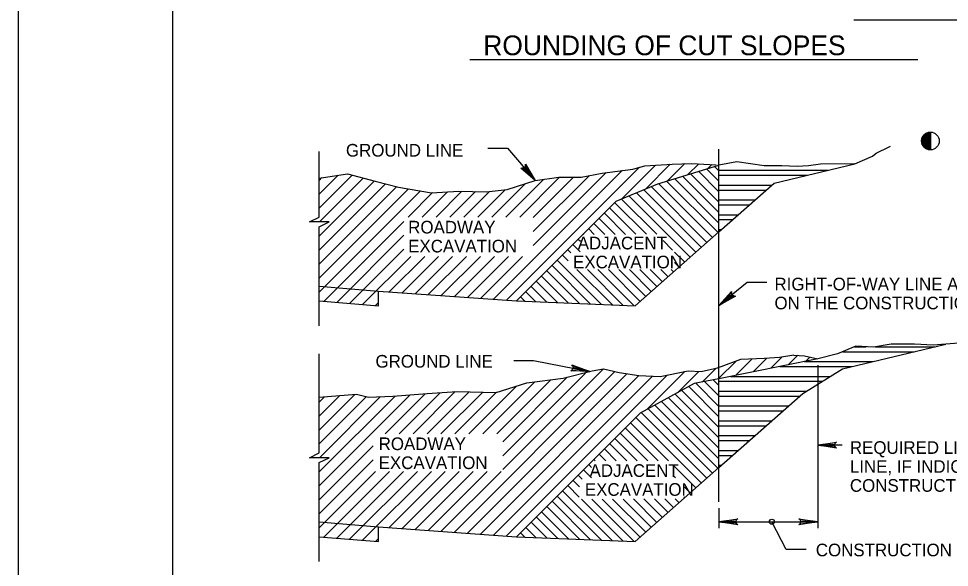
# Model space of a CAD drawing. Extents: x 240 to 1147, y 662 to 1256.
# Drawn here: x 240.4 to 476.2, y 959.9 to 1098.9 of the extents above; entities that cross this region are included whole.
import ezdxf

# ---------------------------------------------------------------- set-up
doc = ezdxf.new("R2010")
doc.units = 0
for name, color, linetype in [('1', 7, 'Continuous'), ('2', 7, 'Continuous'), ('3', 7, 'Continuous'), ('PLT-BNDY', 7, 'Continuous')]:
    doc.layers.add(name, color=color, linetype=linetype)

msp = doc.modelspace()

# ---------------------------------------------------------------- linework, layer by layer
at = {"layer": '1'}
for points in [[(1065.4425, 677.018625), (1065.4425, 1241.018625), (279.4425, 1241.018625), (279.4425, 677.018625), (1065.4425, 677.018625), (1065.4425, 703.377625), (865.4425, 703.377625), (865.4425, 768.055125), (1065.4425, 768.055125), (1065.4425, 797.018625), (865.4425, 797.018625), (865.4425, 677.018625), (944.244, 677.018625), (944.244, 703.377625), (944.244, 677.018625), (1021.244, 677.018625), (1021.244, 703.377625), (1021.244, 691.061125), (1065.4425, 691.061125)], [(368.784, 1061.695875), (368.6445, 1061.352125), (371.309, 1057.877125), (368.784, 1061.695875), (368.784, 1062.002125), (371.309, 1057.877125), (368.30075, 1061.052125), (367.94875, 1060.960375), (371.309, 1057.877125), (367.62375, 1061.006125), (367.94875, 1060.960375)], [(421.69875, 1028.637375), (421.359, 1028.783375), (417.82575, 1026.197875), (421.69875, 1028.637375), (422.005, 1028.631125), (417.82575, 1026.197875), (421.0675, 1029.135375), (420.984, 1029.487375), (417.82575, 1026.197875), (421.03625, 1029.812375), (420.984, 1029.487375)], [(380.75075, 1010.985375), (380.85275, 1010.629125), (385.09875, 1009.558375), (380.75075, 1010.985375), (380.559, 1011.224875), (385.09875, 1009.558375), (380.7695, 1010.181125), (380.55075, 1009.891625), (385.09875, 1009.558375), (380.2675, 1009.724875), (380.55075, 1009.891625)], [(447.3675, 990.327125), (447.1965, 990.656125), (442.82575, 990.897875), (447.3675, 990.327125), (447.59875, 990.127125), (442.82575, 990.897875), (447.1945, 991.112375), (447.35275, 991.437375), (442.82575, 990.897875), (447.59875, 991.656125), (447.35275, 991.437375)], [(422.3675, 970.916625), (422.1965, 971.245875), (417.82575, 971.487375), (422.3675, 970.916625), (422.59875, 970.718625), (417.82575, 971.487375), (422.1945, 971.702125), (422.35275, 972.029125), (417.82575, 971.487375), (422.59875, 972.245875), (422.35275, 972.029125)], [(438.28625, 972.056125), (438.455, 971.729125), (442.82575, 971.487375), (438.28625, 972.056125), (438.05275, 972.256125), (442.82575, 971.487375), (438.459, 971.270875), (438.29875, 970.945875), (442.82575, 971.487375), (438.05275, 970.729125), (438.29875, 970.945875)]]:
    msp.add_lwpolyline(points, dxfattribs=at)
at = {"layer": '2'}
for p, q in [((451.96525, 1098.531125), (499.31125, 1098.531125)), ((354.734, 1088.547875), (468.1715, 1088.547875)), ((471.3675, 1070.122875), (471.3675, 1065.633375)), ((417.82575, 976.524875), (417.82575, 1065.810375)), ((364.00275, 1027.560375), (397.657, 1061.216625)), ((393.16325, 1053.185375), (401.73, 1061.752125)), ((399.282, 1055.768625), (405.48825, 1061.974875)), ((402.3195, 1057.052125), (417.82575, 1061.799875)), ((404.88625, 1057.837375), (409.18825, 1062.139625)), ((409.982, 1059.397875), (412.68825, 1062.104125)), ((415.07775, 1060.958375), (416.02575, 1061.906125)), ((417.82575, 1060.352125), (416.7175, 1061.460375)), ((431.8195, 1057.222875), (452.2715, 1062.091625)), ((316.57575, 1050.843625), (324.9465, 1059.214625)), ((316.57575, 1054.381125), (321.382, 1059.185375)), ((316.57575, 1057.916625), (317.255, 1058.593625)), ((360.70275, 1027.795875), (393.3175, 1060.410375)), ((367.37775, 1048.612375), (377.4675, 1058.704125)), ((370.80275, 1041.431125), (389.23825, 1059.868625)), ((370.80275, 1044.966625), (384.92575, 1059.089625)), ((370.80275, 1048.502125), (381.00275, 1058.704125)), ((417.82575, 1049.743625), (408.5965, 1058.972875)), ((417.82575, 1052.395875), (410.62775, 1059.595875)), ((417.82575, 1055.047875), (412.657, 1060.216625)), ((417.82575, 1057.699875), (414.68825, 1060.837375)), ((417.82575, 1060.462375), (445.43, 1060.462375)), ((417.82575, 1059.212375), (440.18, 1059.212375)), ((316.57575, 1043.772875), (330.52375, 1057.720875)), ((316.57575, 1040.237375), (333.36125, 1057.024875)), ((316.57575, 1036.702125), (336.20275, 1056.329125)), ((316.6425, 1047.374875), (327.734, 1058.468625)), ((360.307, 1048.612375), (368.76125, 1057.068625)), ((363.8425, 1048.612375), (373.39875, 1058.168625)), ((391.8175, 1052.616625), (402.3195, 1057.052125)), ((414.77775, 1042.187375), (400.62775, 1056.337375)), ((416.18625, 1043.429125), (402.507, 1057.110375)), ((417.5945, 1044.672875), (404.53625, 1057.731125)), ((417.82575, 1047.093625), (406.5675, 1058.352125)), ((417.82575, 1044.874875), (431.8195, 1057.222875)), ((417.82575, 1056.712375), (431.2425, 1056.712375)), ((316.57575, 1033.166625), (339.1925, 1055.783375)), ((316.57575, 1029.631125), (342.207, 1055.262375)), ((339.0925, 1048.612375), (345.28, 1054.799875)), ((342.62775, 1048.612375), (349.03825, 1055.022875)), ((346.16325, 1048.612375), (352.7215, 1055.170875)), ((349.69875, 1048.612375), (356.155, 1055.068625)), ((353.234, 1048.612375), (359.709, 1055.087375)), ((356.7715, 1048.612375), (363.71325, 1055.554125)), ((410.55275, 1038.458375), (395.034, 1053.974875)), ((411.96125, 1039.699875), (396.89875, 1054.762375)), ((413.3695, 1040.943625), (398.76125, 1055.549875)), ((417.82575, 1055.462375), (429.82575, 1055.462375)), ((391.8175, 1052.616625), (366.57575, 1027.374875)), ((399.43625, 1044.268625), (391.45275, 1052.252125)), ((402.07375, 1044.283375), (393.1695, 1053.187375)), ((417.82575, 1052.962375), (426.9925, 1052.962375)), ((417.82575, 1051.712375), (425.57575, 1051.712375)), ((394.16125, 1044.241625), (388.80075, 1049.599875)), ((396.79875, 1044.256125), (390.12775, 1050.927125)), ((417.82575, 1049.212375), (422.7425, 1049.212375)), ((317.757, 1027.277125), (338.01125, 1047.531125)), ((388.884, 1044.214625), (386.15075, 1046.949875)), ((391.52375, 1044.229125), (387.47575, 1048.274875)), ((417.82575, 1047.962375), (421.32575, 1047.962375)), ((386.2465, 1044.199875), (384.82375, 1045.624875)), ((396.57575, 1026.124875), (417.82575, 1044.874875)), ((417.82575, 1045.462375), (418.4925, 1045.462375)), ((321.0215, 1027.006125), (338.01125, 1043.995875)), ((382.72375, 1042.420875), (382.1715, 1042.972875)), ((383.609, 1044.187375), (383.49875, 1044.297875)), ((406.082, 1040.274875), (403.69875, 1042.658375)), ((324.284, 1026.733375), (338.01125, 1040.460375)), ((380.30275, 1039.537375), (379.5195, 1040.320875)), ((382.66525, 1039.829125), (380.8465, 1041.645875)), ((409.1425, 1037.214625), (406.582, 1039.774875)), ((327.54875, 1026.462375), (339.759, 1038.672875)), ((334.30275, 1029.681125), (343.2945, 1038.672875)), ((337.60275, 1029.445875), (346.83, 1038.672875)), ((340.90275, 1029.210375), (350.36525, 1038.672875)), ((344.20275, 1028.974875), (353.90075, 1038.672875)), ((347.50275, 1028.737375), (357.43625, 1038.672875)), ((350.80275, 1028.502125), (360.9715, 1038.672875)), ((354.10275, 1028.266625), (364.509, 1038.672875)), ((357.40275, 1028.031125), (368.0445, 1038.672875)), ((388.057, 1026.481125), (376.8695, 1037.668625)), ((379.6675, 1037.522875), (378.1945, 1038.993625)), ((382.52375, 1026.712375), (374.2175, 1035.016625)), ((385.29025, 1026.595875), (375.5425, 1036.343625)), ((390.82375, 1026.366625), (381.86525, 1035.322875)), ((393.59025, 1026.249875), (384.5175, 1035.322875)), ((396.357, 1026.135375), (387.1695, 1035.322875)), ((397.87375, 1027.270875), (389.8215, 1035.322875)), ((399.282, 1028.514625), (392.4715, 1035.322875)), ((400.69025, 1029.756125), (395.12375, 1035.322875)), ((402.09875, 1030.999875), (397.77575, 1035.322875)), ((403.509, 1032.241625), (400.42775, 1035.322875)), ((404.9175, 1033.485375), (403.08, 1035.322875)), ((406.32575, 1034.729125), (405.732, 1035.322875)), ((407.734, 1035.970875), (406.582, 1037.122875)), ((379.757, 1026.827125), (372.8925, 1033.691625)), ((316.57575, 1031.124875), (331.57575, 1029.874875)), ((374.2215, 1027.058375), (370.24025, 1031.039625)), ((376.98825, 1026.941625), (371.56525, 1032.364625)), ((331.57575, 1026.124875), (331.57575, 1029.874875)), ((331.57575, 1029.874875), (366.57575, 1027.374875)), ((368.68825, 1027.287375), (367.58825, 1028.387375)), ((371.455, 1027.172875), (368.91325, 1029.714625)), ((316.57575, 1027.374875), (331.57575, 1026.124875)), ((330.81125, 1026.189625), (331.57575, 1026.954125)), ((366.57575, 1027.374875), (396.57575, 1026.124875)), ((449.07575, 1010.204125), (475.32575, 1016.454125)), ((447.82575, 1013.954125), (442.82575, 1012.704125)), ((449.2195, 1014.541625), (467.2925, 1014.541625)), ((452.18825, 1015.791625), (455.07775, 1015.791625)), ((457.44025, 1015.791625), (472.5425, 1015.791625)), ((442.82575, 1012.704125), (417.82575, 1007.704125)), ((417.82575, 1007.82234), (422.178154, 1012.174743)), ((422.097399, 1008.558455), (426.242198, 1012.703254)), ((426.516817, 1009.442338), (429.934303, 1012.859825)), ((430.936234, 1010.326222), (433.779069, 1013.169057)), ((435.355651, 1011.210105), (437.771874, 1013.626328)), ((439.51325, 1012.041625), (456.7925, 1012.041625)), ((439.775069, 1012.093989), (440.865799, 1013.184719)), ((350.80275, 968.831125), (391.47575, 1009.504125)), ((363.11125, 984.677125), (388.6195, 1010.183375)), ((363.11125, 988.212375), (384.03625, 1009.135375)), ((399.53625, 999.887375), (409.20275, 1009.554125)), ((407.31325, 1004.131125), (412.71125, 1009.527125)), ((413.57375, 1006.854125), (417.11125, 1010.391625)), ((433.26325, 1010.791625), (451.5425, 1010.791625)), ((439.07575, 1003.954125), (449.07575, 1010.204125)), ((442.82575, 1011.104125), (442.82575, 969.887375)), ((354.10275, 968.595875), (394.47575, 1008.968625)), ((357.40275, 968.360375), (397.5675, 1008.527125)), ((358.0195, 993.727125), (371.16525, 1006.872875)), ((360.70275, 968.124875), (400.955, 1008.377125)), ((361.555, 993.727125), (375.22775, 1007.399875)), ((363.11125, 991.747875), (379.41325, 1008.047875)), ((364.00275, 967.889625), (404.7695, 1008.656125)), ((417.82575, 1007.704125), (411.57575, 1006.454125)), ((417.82575, 1003.331125), (414.182, 1006.974875)), ((417.82575, 1005.983375), (416.3925, 1007.418625)), ((417.82575, 1007.041625), (444.01525, 1007.041625)), ((420.76325, 1008.291625), (446.01525, 1008.291625)), ((340.3425, 993.727125), (351.05275, 1004.437375)), ((343.87775, 993.727125), (354.5465, 1004.395875)), ((347.41325, 993.727125), (357.99875, 1004.312375)), ((354.484, 993.727125), (366.5675, 1005.810375)), ((411.57575, 1006.454125), (397.82575, 998.954125)), ((417.82575, 995.377125), (408.45275, 1004.749875)), ((417.82575, 998.029125), (410.1675, 1005.687375)), ((417.82575, 1000.681125), (411.9715, 1006.533375)), ((417.82575, 1004.541625), (440.01525, 1004.541625)), ((316.57575, 994.708375), (325.58825, 1003.720875)), ((316.57575, 980.566625), (339.607, 1003.597875)), ((316.57575, 998.243625), (321.76125, 1003.431125)), ((316.57575, 984.102125), (335.79025, 1003.318625)), ((316.57575, 991.172875), (328.56125, 1003.158375)), ((316.57575, 1001.781125), (317.93625, 1003.139625)), ((316.6425, 987.704125), (332.0925, 1003.154125)), ((333.2715, 993.727125), (343.4215, 1003.877125)), ((336.807, 993.727125), (347.23625, 1004.156125)), ((350.94875, 993.727125), (361.4695, 1004.247875)), ((417.82575, 987.420875), (403.305, 1001.943625)), ((417.82575, 990.072875), (405.0215, 1002.879125)), ((417.82575, 992.724875), (406.73625, 1003.814625)), ((417.82575, 985.204125), (439.07575, 1003.954125)), ((417.82575, 1003.291625), (438.32575, 1003.291625)), ((416.18625, 983.758375), (399.87375, 1000.070875)), ((417.5945, 985.002125), (401.58825, 1001.008375)), ((417.82575, 1000.791625), (435.4925, 1000.791625)), ((397.82575, 998.954125), (366.57575, 967.704125)), ((413.3695, 981.272875), (396.757, 997.885375)), ((414.77775, 982.514625), (398.157, 999.135375)), ((417.82575, 999.541625), (434.07575, 999.541625)), ((402.4195, 986.918625), (394.105, 995.233375)), ((405.0715, 986.918625), (395.43, 996.560375)), ((417.82575, 997.041625), (431.2425, 997.041625)), ((417.82575, 995.791625), (429.82575, 995.791625)), ((397.11525, 986.918625), (391.45275, 992.581125)), ((399.7675, 986.918625), (392.77775, 993.908375)), ((417.82575, 993.291625), (426.9925, 993.291625)), ((316.57575, 977.031125), (330.21525, 990.670875)), ((394.46525, 986.918625), (390.12775, 991.256125)), ((417.82575, 992.041625), (425.57575, 992.041625)), ((389.16125, 986.918625), (387.47575, 988.604125)), ((391.81125, 986.918625), (388.80075, 989.929125)), ((417.82575, 989.541625), (422.7425, 989.541625)), ((417.82575, 988.291625), (421.32575, 988.291625)), ((316.57575, 973.495875), (330.21525, 987.135375)), ((385.5425, 985.235375), (384.82375, 985.952125)), ((386.509, 986.918625), (386.15075, 987.279125)), ((411.96125, 980.029125), (406.4425, 985.547875)), ((417.82575, 985.791625), (418.4925, 985.791625)), ((316.57575, 969.960375), (330.834, 984.218625)), ((317.757, 967.606125), (334.3695, 984.218625)), ((321.0215, 967.335375), (337.905, 984.218625)), ((324.284, 967.062375), (341.44025, 984.218625)), ((327.54875, 966.791625), (344.97575, 984.218625)), ((334.30275, 970.010375), (348.51125, 984.218625)), ((337.60275, 969.774875), (352.0465, 984.218625)), ((340.90275, 969.539625), (355.582, 984.218625)), ((344.20275, 969.302125), (359.1175, 984.218625)), ((347.50275, 969.066625), (362.65275, 984.218625)), ((383.20075, 982.272875), (382.1715, 983.302125)), ((385.5425, 982.583375), (383.49875, 984.627125)), ((396.57575, 966.454125), (417.82575, 985.204125)), ((382.509, 980.312375), (380.8465, 981.974875)), ((406.77575, 982.562375), (406.37775, 982.960375)), ((390.82375, 966.693625), (378.1945, 979.322875)), ((382.455, 977.714625), (379.5195, 980.649875)), ((410.55275, 978.787375), (408.932, 980.406125)), ((385.29025, 966.924875), (375.5425, 976.670875)), ((388.057, 966.810375), (376.8695, 977.997875)), ((393.59025, 966.579125), (382.9715, 977.197875)), ((396.357, 966.464625), (385.61325, 977.208375)), ((397.87375, 967.599875), (388.255, 977.218625)), ((399.282, 968.843625), (390.8945, 977.229125)), ((400.69025, 970.085375), (393.53625, 977.239625)), ((402.09875, 971.329125), (396.17775, 977.252125)), ((403.509, 972.570875), (398.8175, 977.262375)), ((404.9175, 973.814625), (401.459, 977.272875)), ((406.32575, 975.058375), (404.10075, 977.283375)), ((407.734, 976.299875), (406.74025, 977.293625)), ((409.1425, 977.543625), (408.932, 977.754125)), ((379.757, 967.156125), (372.8925, 974.020875)), ((382.52375, 967.039625), (374.2175, 975.345875)), ((417.82575, 974.924875), (417.82575, 969.887375)), ((316.57575, 971.454125), (331.57575, 970.204125)), ((374.2215, 967.387375), (370.24025, 971.368625)), ((376.98825, 967.270875), (371.56525, 972.693625)), ((417.82575, 971.487375), (442.82575, 971.487375)), ((331.57575, 966.454125), (331.57575, 970.204125)), ((331.57575, 970.204125), (366.57575, 967.704125)), ((371.455, 967.502125), (368.91325, 970.043625)), ((316.57575, 967.704125), (331.57575, 966.454125)), ((330.81125, 966.518625), (331.57575, 967.283375)), ((366.57575, 967.704125), (396.57575, 966.454125)), ((368.68825, 967.616625), (367.58825, 968.716625))]:
    msp.add_line(p, q, dxfattribs=at)
for points in [[(359.28625, 1066.060375), (364.28625, 1066.060375), (371.309, 1057.877125)], [(452.2715, 1062.091625), (456.72775, 1064.043625), (457.60275, 1064.781125), (460.95075, 1066.399875), (461.259, 1066.529125)], [(316.57575, 1021.124875), (316.57575, 1033.624875), (316.57575, 1046.124875), (319.07575, 1047.374875), (314.07575, 1047.374875), (316.57575, 1048.624875), (316.57575, 1065.222875)], [(316.57575, 1058.497875), (323.77375, 1059.529125), (330.709, 1057.670875), (336.62575, 1056.227125), (344.99025, 1054.781125), (351.92775, 1055.195875), (358.86325, 1054.987375), (364.1675, 1055.608375), (371.309, 1057.877125), (377.22575, 1058.704125), (382.93825, 1058.704125), (388.2425, 1059.735375), (395.9945, 1060.766625), (399.055, 1061.593625), (405.9925, 1062.006125), (410.88825, 1062.212375), (417.107, 1061.841625)], [(452.2715, 1062.091625), (443.53, 1062.006125), (440.4715, 1061.593625), (437.61525, 1061.385375), (433.73825, 1061.593625), (429.24875, 1061.593625), (422.31325, 1062.624875), (417.82575, 1061.799875), (417.63, 1061.810375)], [(429.92775, 1032.020875), (424.92775, 1032.020875), (417.82575, 1026.197875)], [(487.44025, 1018.077125), (482.2465, 1017.360375), (480.832, 1016.883375), (475.32575, 1016.454125), (472.10075, 1016.166625), (467.38, 1016.406125), (461.48, 1016.406125), (456.9965, 1015.689625), (452.51125, 1015.929125), (447.82575, 1013.954125), (447.82575, 1013.954125)], [(316.57575, 961.454125), (316.57575, 973.954125), (316.57575, 986.454125), (319.07575, 987.704125), (314.07575, 987.704125), (316.57575, 988.954125), (316.57575, 1013.954125)], [(365.82775, 1012.335375), (370.82775, 1012.335375), (385.09875, 1009.558375)], [(436.8195, 1013.681125), (433.159, 1013.064625), (429.384, 1012.824875), (423.24875, 1012.587375), (418.2925, 1010.677125), (417.4945, 1010.485375)], [(436.8195, 1013.681125), (439.46125, 1013.529125), (442.82575, 1012.704125)], [(316.57575, 1003.037375), (326.01525, 1003.754125), (329.084, 1003.037375), (335.2195, 1003.274875), (343.95275, 1003.991625), (351.50275, 1004.468625), (361.41525, 1004.231125), (369.20275, 1006.618625), (378.407, 1007.812375), (385.72375, 1009.720875), (388.555, 1010.199875), (392.5675, 1009.243625), (397.52375, 1008.529125), (402.95275, 1008.289625), (410.032, 1009.720875), (413.33625, 1009.483375), (417.4945, 1010.485375)], [(449.02575, 990.897875), (442.82575, 990.897875)], [(439.8695, 964.431125), (434.8695, 964.431125), (431.234, 971.487375)]]:
    msp.add_lwpolyline(points, dxfattribs=at)
for centre, radius in [((471.368242, 1067.879088), 2.24484), ((431.234833, 971.486958), 0.632169)]:
    msp.add_circle(centre, radius, dxfattribs=at)
for radius in [2.104538, 1.964235, 1.823933, 1.68363, 1.543328, 1.403025, 1.262723, 1.12242, 0.982118, 0.841815, 0.701513, 0.56121, 0.420908, 0.280605, 0.140303]:
    msp.add_arc((471.368242, 1067.879088), radius, 89.99999722, 269.99999722, dxfattribs=at)
at = {"layer": 'PLT-BNDY'}
msp.add_lwpolyline([(240.4425, 1256.018625), (1081.4425, 1256.018625), (1081.4425, 662.018625), (240.4425, 662.018625)], close=True, dxfattribs=at)

# ---------------------------------------------------------------- texts
at = {"layer": '3'}
for s, height, p in [('ROUNDING OF CUT SLOPES', 4.9998615, (358.134, 1089.593625)), ('GROUND LINE', 3.1999875, (323.3465, 1063.929125)), ('ROADWAY', 3.1999875, (339.11525, 1044.466625)), ('EXCAVATION', 3.1999875, (339.11525, 1039.666625)), (' ADJACENT', 3.1999875, (380.87375, 1040.437375)), ('EXCAVATION', 3.1999875, (380.87375, 1035.637375)), ('RIGHT-OF-WAY LINE AS INDICATED', 3.1999875, (431.88625, 1030.060375)), ('ON THE CONSTRUCTION DRAWINGS.', 3.1999875, (431.88625, 1025.260375)), ('GROUND LINE', 3.1999875, (330.82775, 1010.504125)), ('ROADWAY', 3.1999875, (331.634, 989.622875)), ('REQUIRED LIMIT OF SLOPE', 3.1999875, (450.98625, 988.670875)), ('EXCAVATION', 3.1999875, (331.634, 984.822875)), (' ADJACENT', 3.1999875, (383.859, 982.847875)), ('LINE, IF INDICATED ON THE', 3.1999875, (450.98625, 983.870875)), ('EXCAVATION', 3.1999875, (383.859, 978.049875)), ('CONSTRUCTION DRAWINGS.', 3.1999875, (450.98625, 979.070875)), ('CONSTRUCTION OR SLOPE EASEMENT', 3.1999875, (442.35275, 962.735375))]:
    msp.add_text(s, height=height, dxfattribs=at).set_placement(p)

doc.saveas('drawing.dxf')
